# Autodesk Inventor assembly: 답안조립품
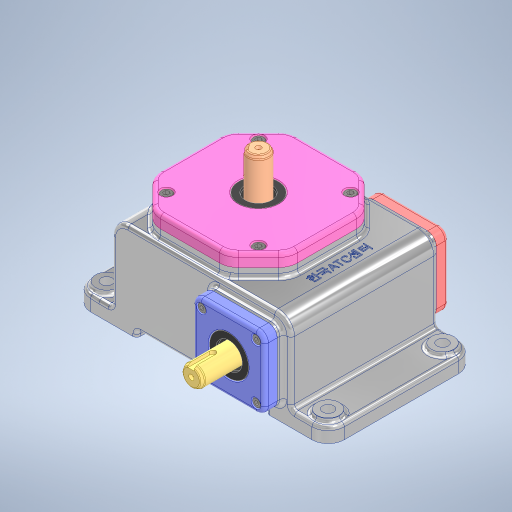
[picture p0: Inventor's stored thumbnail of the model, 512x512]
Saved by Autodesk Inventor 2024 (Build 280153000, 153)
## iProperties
Created: 2026-02
Part Number: 답안조립품
Document SubType Name: Assembly
Designer: 2-10
Author: 2-10
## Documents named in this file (14)
- C:\Users\2-10\Desktop\760203V1002\답안조립품.iam
- C:\Users\2-10\Desktop\760203V1002\본체.ipt
- C:\Users\2-10\Desktop\760203V1002\웜 샤프트 copy.ipt
- C:\Users\2-10\Desktop\760203V1002\웜 휠 copy.ipt
- C:\Users\2-10\Desktop\760203V1002\웜 휠 커버 copy.ipt
- C:\Users\2-10\Desktop\760203V1002\축 copy.ipt
- C:\Users\2-10\Desktop\760203V1002\칼라 copy.ipt
- C:\Users\2-10\Desktop\760203V1002\테이퍼 롤러 베어링 30203 copy.ipt
- C:\Users\2-10\Desktop\760203V1002\평행 키 5x5x16 copy.ipt
- C:\Users\2-10\Desktop\760203V1002\6각 구멍붙이 볼트 M4x10 copy.ipt
- C:\Users\2-10\Desktop\760203V1002\6각 구멍붙이 볼트 M5x10 copy.ipt
- C:\Users\2-10\Desktop\760203V1002\뒷커버 copy.ipt
- C:\Users\2-10\Desktop\760203V1002\앞커버 copy.ipt
- C:\Users\2-10\Desktop\760203V1002\오일 실 17 32 8 copy.ipt
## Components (12 placed, 2 different names)
1. 6각 구멍붙이 볼트 M4x10 copy:1
2. 6각 구멍붙이 볼트 M5x10 copy:1
3. 6각 구멍붙이 볼트 M4x10 copy:2
4. 6각 구멍붙이 볼트 M4x10 copy:3
5. 6각 구멍붙이 볼트 M4x10 copy:4
6. 6각 구멍붙이 볼트 M4x10 copy:5
7. 6각 구멍붙이 볼트 M4x10 copy:6
8. 6각 구멍붙이 볼트 M4x10 copy:7
9. 6각 구멍붙이 볼트 M5x10 copy:2
10. 6각 구멍붙이 볼트 M5x10 copy:3
11. 6각 구멍붙이 볼트 M5x10 copy:4
12. 6각 구멍붙이 볼트 M4x10 copy:8
